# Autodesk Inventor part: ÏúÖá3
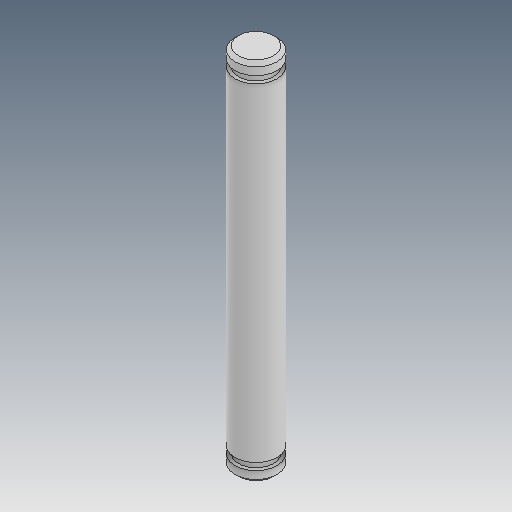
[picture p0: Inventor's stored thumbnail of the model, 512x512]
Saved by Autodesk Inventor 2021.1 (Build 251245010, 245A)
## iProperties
Created: 2014-12
Part Number: ÏúÖá3
Material: Ogólny
Document SubType Name: Modeling
Designer: user
Density: 1 g/cm^3
Appearance: Domyślna
Author: user
Revision Number: ÈÎºÎ
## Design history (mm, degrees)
feature "ÊäÈë1"
node "Bryła1"
